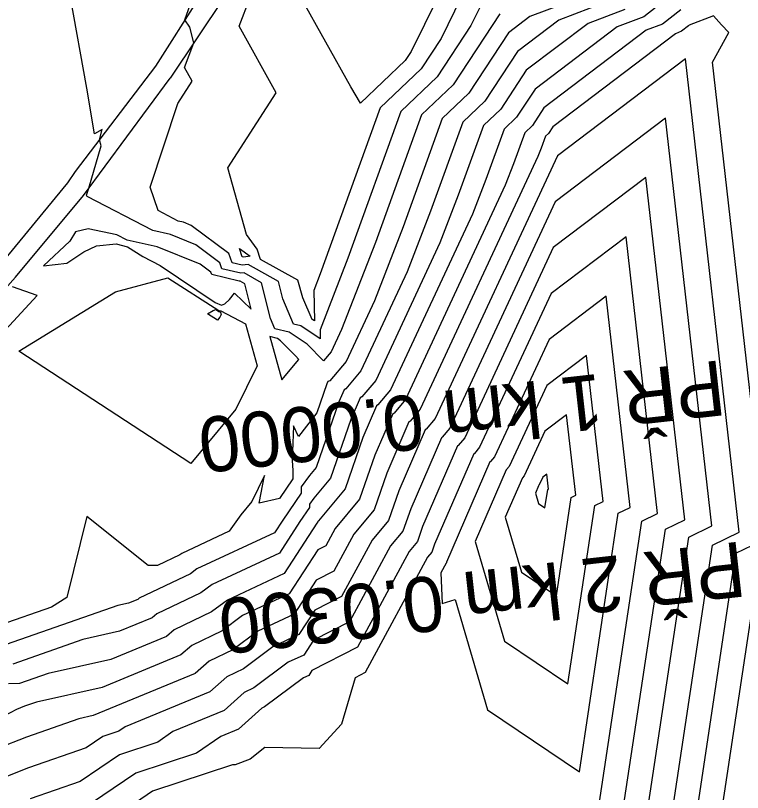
# Model space of a CAD drawing. Extents: x -549394 to -546608, y -1037055 to -1033629.
# Drawn here: x -547735.2 to -547615.7, y -1035584.9 to -1035457.1 of the extents above; entities that cross this region are included whole.
import ezdxf

# ---------------------------------------------------------------- set-up
doc = ezdxf.new("R2010")
doc.units = 0
for name, color, linetype in [('hlavni_vrst', 7, 'Continuous'), ('hrana_L', 7, 'Continuous'), ('norm_vrst', 7, 'Continuous'), ('x_popis_pricne_rezy_C111', 7, 'Continuous')]:
    doc.layers.add(name, color=color, linetype=linetype)

msp = doc.modelspace()

# ---------------------------------------------------------------- linework, layer by layer
at = {"layer": 'hlavni_vrst'}
for p, q in [((-547664.28, -1035451.11), (-547670.13, -1035463.03)), ((-547680.08, -1035468.83), (-547689.44, -1035452.02)), ((-547638.14, -1035454.93), (-547645.86, -1035457.85)), ((-547645.86, -1035457.85), (-547652.67, -1035463.03)), ((-547670.13, -1035463.03), (-547671.12, -1035464.52)), ((-547652.67, -1035463.03), (-547658.05, -1035471.18)), ((-547671.12, -1035464.52), (-547678.47, -1035471.52)), ((-547625.05, -1035464.23), (-547646.1, -1035480.2)), ((-547616.21, -1035542.07), (-547625.05, -1035464.23)), ((-547678.47, -1035471.52), (-547680.08, -1035468.83)), ((-547658.05, -1035471.18), (-547661.66, -1035474.62)), ((-547661.66, -1035474.62), (-547666.95, -1035489.27)), ((-547646.1, -1035480.2), (-547666.22, -1035523.41)), ((-547666.95, -1035489.27), (-547670.82, -1035499.26)), ((-547670.82, -1035499.26), (-547678.41, -1035515.56)), ((-547641.33, -1035513.01), (-547647.82, -1035517.94)), ((-547638.6, -1035537.02), (-547641.33, -1035513.01)), ((-547678.41, -1035515.56), (-547680.9, -1035518.5)), ((-547647.82, -1035517.94), (-547654.03, -1035531.27)), ((-547681.17, -1035518.65), (-547682.03, -1035520.64)), ((-547680.9, -1035518.5), (-547681.17, -1035518.65)), ((-547682.03, -1035520.64), (-547685.78, -1035531.46)), ((-547666.22, -1035523.41), (-547667.69, -1035525.15)), ((-547667.85, -1035525.24), (-547672.2, -1035535.3)), ((-547667.69, -1035525.15), (-547667.85, -1035525.24)), ((-547685.78, -1035531.46), (-547686.88, -1035532.78)), ((-547654.53, -1035531.83), (-547659.62, -1035543.61)), ((-547654.48, -1035531.8), (-547654.53, -1035531.83)), ((-547654.03, -1035531.27), (-547654.48, -1035531.8)), ((-547686.88, -1035532.78), (-547688.23, -1035534.65)), ((-547688.23, -1035534.65), (-547688.22, -1035535.67)), ((-547688.22, -1035535.67), (-547691.27, -1035540.11)), ((-547672.2, -1035535.3), (-547673.88, -1035540.16)), ((-547639.96, -1035537.69), (-547638.6, -1035537.02)), ((-547644.39, -1035567.05), (-547639.96, -1035537.69)), ((-547691.27, -1035540.11), (-547692.61, -1035542.19)), ((-547673.88, -1035540.16), (-547676.56, -1035543.39)), ((-547692.61, -1035542.19), (-547705.37, -1035548.14)), ((-547620.62, -1035544.22), (-547616.21, -1035542.07)), ((-547676.56, -1035543.39), (-547681.58, -1035552.67)), ((-547659.62, -1035543.61), (-547654.8, -1035560.01)), ((-547628.56, -1035596.95), (-547620.62, -1035544.22)), ((-547706.45, -1035548.95), (-547714.87, -1035552.95)), ((-547705.37, -1035548.14), (-547706.45, -1035548.95)), ((-547681.58, -1035552.67), (-547685.99, -1035554.91)), ((-547716.64, -1035553.78), (-547718.39, -1035554.17)), ((-547715.08, -1035553.14), (-547716.64, -1035553.78)), ((-547714.87, -1035552.95), (-547715.08, -1035553.14)), ((-547718.39, -1035554.17), (-547736.73, -1035560.59)), ((-547685.99, -1035554.91), (-547688.6, -1035558.94)), ((-547688.6, -1035558.94), (-547692.88, -1035560.94)), ((-547654.8, -1035560.01), (-547644.39, -1035567.05)), ((-547692.88, -1035560.94), (-547697.74, -1035564.59)), ((-547697.74, -1035564.59), (-547700.47, -1035565.89)), ((-547700.47, -1035565.89), (-547703.27, -1035568.38)), ((-547703.27, -1035568.38), (-547717.17, -1035574.12)), ((-547717.17, -1035574.12), (-547718.22, -1035574.85)), ((-547720.85, -1035575.72), (-547723.56, -1035577.55)), ((-547718.22, -1035574.85), (-547720.85, -1035575.72)), ((-547723.56, -1035577.55), (-547733.09, -1035580.87)), ((-547733.09, -1035580.87), (-547743.07, -1035584.83))]:
    msp.add_line(p, q, dxfattribs=at)
at = {"layer": 'hrana_L'}
for p, q in [((-547699.54, -1035445.41), (-547712.17, -1035465.45)), ((-547696.51, -1035447.59), (-547709.78, -1035467.43)), ((-547712.17, -1035465.45), (-547725.38, -1035482.77)), ((-547724.03, -1035486.73), (-547709.78, -1035467.43)), ((-547725.38, -1035482.77), (-547726.66, -1035484.61)), ((-547726.66, -1035484.61), (-547737.85, -1035498.19)), ((-547735.19, -1035500.12), (-547724.03, -1035486.73)), ((-547747.65, -1035514.01), (-547735.19, -1035500.12))]:
    msp.add_line(p, q, dxfattribs=at)
at = {"layer": 'norm_vrst'}
for p, q in [((-547698.44, -1035458.84), (-547694.5, -1035448.65)), ((-547723.48, -1035469.06), (-547726.4, -1035452.64)), ((-547661.36, -1035453), (-547665.23, -1035460.9)), ((-547641.26, -1035453.73), (-547650.65, -1035457.29)), ((-547627.1, -1035453.54), (-547631.91, -1035457.32)), ((-547707.37, -1035457.83), (-547706.2, -1035454.57)), ((-547658.44, -1035454.9), (-547660.33, -1035458.76)), ((-547655.57, -1035456.83), (-547663.27, -1035468.52)), ((-547635.03, -1035456.12), (-547641.07, -1035458.41)), ((-547625.83, -1035456.18), (-547628.8, -1035458.51)), ((-547706.52, -1035459.01), (-547707.37, -1035457.83)), ((-547650.65, -1035457.29), (-547654.12, -1035459.93)), ((-547631.91, -1035457.32), (-547636.28, -1035458.97)), ((-547620.46, -1035457.13), (-547624.42, -1035458.69)), ((-547619.15, -1035458.65), (-547620.46, -1035457.13)), ((-547705.86, -1035461.57), (-547706.52, -1035459.01)), ((-547692.32, -1035469.82), (-547698.44, -1035458.84)), ((-547660.33, -1035458.76), (-547665.89, -1035467.19)), ((-547641.07, -1035458.41), (-547651.22, -1035466.12)), ((-547636.28, -1035458.97), (-547649.77, -1035469.22)), ((-547628.8, -1035458.51), (-547631.49, -1035459.53)), ((-547624.56, -1035458.82), (-547625.68, -1035459.7)), ((-547624.42, -1035458.69), (-547624.56, -1035458.82)), ((-547617.94, -1035459.88), (-547619.15, -1035458.65)), ((-547654.12, -1035459.93), (-547660.66, -1035469.85)), ((-547631.49, -1035459.53), (-547648.32, -1035472.31)), ((-547626.7, -1035460.09), (-547646.87, -1035475.41)), ((-547625.68, -1035459.7), (-547626.7, -1035460.09)), ((-547620.63, -1035464.77), (-547617.94, -1035459.88)), ((-547707.44, -1035465.66), (-547705.86, -1035461.57)), ((-547665.23, -1035460.9), (-547668.5, -1035465.85)), ((-547706.18, -1035467.92), (-547707.44, -1035465.66)), ((-547668.5, -1035465.85), (-547675.25, -1035472.28)), ((-547611.73, -1035543.08), (-547620.63, -1035464.77)), ((-547665.89, -1035467.19), (-547671.85, -1035472.87)), ((-547651.22, -1035466.12), (-547655.43, -1035472.51)), ((-547708.54, -1035471.56), (-547706.18, -1035467.92)), ((-547722.23, -1035476.54), (-547723.48, -1035469.06)), ((-547663.27, -1035468.52), (-547668.45, -1035473.45)), ((-547649.77, -1035469.22), (-547652.82, -1035473.84)), ((-547700.32, -1035482.14), (-547692.32, -1035469.82)), ((-547660.66, -1035469.85), (-547665.06, -1035474.04)), ((-547713.06, -1035485.32), (-547708.54, -1035471.56)), ((-547675.25, -1035472.28), (-547685.11, -1035499.6)), ((-547671.85, -1035472.87), (-547680.57, -1035497.02)), ((-547668.45, -1035473.45), (-547676.03, -1035494.44)), ((-547655.43, -1035472.51), (-547658.27, -1035475.21)), ((-547648.32, -1035472.31), (-547650.2, -1035475.17)), ((-547665.06, -1035474.04), (-547671.49, -1035491.85)), ((-547652.82, -1035473.84), (-547654.87, -1035475.8)), ((-547628.31, -1035473.99), (-547646.45, -1035487.75)), ((-547620.69, -1035541.06), (-547628.31, -1035473.99)), ((-547720.95, -1035475.87), (-547722.23, -1035476.54)), ((-547721.4, -1035477.56), (-547720.95, -1035475.87)), ((-547658.27, -1035475.21), (-547662.41, -1035486.68)), ((-547654.87, -1035475.8), (-547657.87, -1035484.1)), ((-547650.2, -1035475.17), (-547651.47, -1035476.38)), ((-547646.87, -1035475.41), (-547647.59, -1035476.5)), ((-547651.47, -1035476.38), (-547653.33, -1035481.52)), ((-547648.08, -1035476.97), (-547648.79, -1035478.93)), ((-547647.59, -1035476.5), (-547648.08, -1035476.97)), ((-547723.13, -1035485.51), (-547721.1, -1035478.56)), ((-547721.1, -1035478.56), (-547721.4, -1035477.56)), ((-547648.79, -1035478.93), (-547649.31, -1035480.27)), ((-547649.31, -1035480.27), (-547668.66, -1035521.84)), ((-547697.25, -1035493.12), (-547700.32, -1035482.14)), ((-547653.33, -1035481.52), (-547654.68, -1035485.02)), ((-547631.56, -1035483.75), (-547646.79, -1035495.29)), ((-547625.17, -1035540.05), (-547631.56, -1035483.75)), ((-547654.68, -1035485.02), (-547671.09, -1035520.27)), ((-547657.87, -1035484.1), (-547660.06, -1035489.77)), ((-547723.51, -1035486.66), (-547723.13, -1035485.51)), ((-547711.76, -1035489.2), (-547713.06, -1035485.32)), ((-547723.45, -1035486.85), (-547723.51, -1035486.66)), ((-547712.65, -1035492.49), (-547723.45, -1035486.85)), ((-547662.41, -1035486.68), (-547665.44, -1035494.51)), ((-547646.45, -1035487.75), (-547663.78, -1035524.99)), ((-547708.46, -1035490.92), (-547711.76, -1035489.2)), ((-547660.06, -1035489.77), (-547673.53, -1035518.7)), ((-547707.57, -1035491.11), (-547708.46, -1035490.92)), ((-547706.3, -1035491.63), (-547707.57, -1035491.11)), ((-547725.36, -1035492.66), (-547726.26, -1035494.21)), ((-547723.26, -1035492.22), (-547725.36, -1035492.66)), ((-547718.53, -1035493.17), (-547723.26, -1035492.22)), ((-547709.73, -1035493.12), (-547712.65, -1035492.49)), ((-547700.13, -1035496.25), (-547706.3, -1035491.63)), ((-547671.49, -1035491.85), (-547676.2, -1035504.01)), ((-547716.84, -1035494.05), (-547718.53, -1035493.17)), ((-547705.56, -1035494.82), (-547709.73, -1035493.12)), ((-547695.49, -1035495.53), (-547697.25, -1035493.12)), ((-547634.82, -1035493.5), (-547647.13, -1035502.84)), ((-547629.65, -1035539.04), (-547634.82, -1035493.5)), ((-547726.26, -1035494.21), (-547730.58, -1035498.27)), ((-547723.99, -1035495.99), (-547721.9, -1035494.97)), ((-547721.9, -1035494.97), (-547718.66, -1035494.68)), ((-547718.66, -1035494.68), (-547716.78, -1035495.16)), ((-547711.89, -1035495.13), (-547716.84, -1035494.05)), ((-547716.78, -1035495.16), (-547714.25, -1035496.75)), ((-547704.83, -1035498), (-547711.89, -1035495.13)), ((-547701.61, -1035497.78), (-547705.56, -1035494.82)), ((-547676.03, -1035494.44), (-547681.58, -1035508.76)), ((-547665.44, -1035494.51), (-547675.97, -1035517.13)), ((-547646.79, -1035495.29), (-547661.34, -1035526.56)), ((-547726.75, -1035497.82), (-547723.99, -1035495.99)), ((-547699.59, -1035497.78), (-547700.13, -1035496.25)), ((-547697.92, -1035496.81), (-547698.4, -1035495.42)), ((-547698.4, -1035495.42), (-547696.63, -1035496.71)), ((-547694.93, -1035497.25), (-547695.49, -1035495.53)), ((-547730.58, -1035498.27), (-547726.75, -1035497.82)), ((-547714.25, -1035496.75), (-547711.43, -1035498.22)), ((-547701.27, -1035498.76), (-547701.61, -1035497.78)), ((-547697.93, -1035498.18), (-547699.59, -1035497.78)), ((-547697.67, -1035496.86), (-547697.92, -1035496.81)), ((-547696.63, -1035496.71), (-547697.67, -1035496.86)), ((-547688.8, -1035500.63), (-547694.93, -1035497.25)), ((-547680.57, -1035497.02), (-547685.13, -1035508.79)), ((-547711.43, -1035498.22), (-547702.38, -1035504.33)), ((-547703.1, -1035499.3), (-547704.83, -1035498)), ((-547698.18, -1035499.5), (-547701.27, -1035498.76)), ((-547696.97, -1035498.04), (-547697.93, -1035498.18)), ((-547691.97, -1035500.87), (-547696.97, -1035498.04)), ((-547718.76, -1035502.57), (-547710.18, -1035500.27)), ((-547710.18, -1035500.27), (-547701.8, -1035505.6)), ((-547702.95, -1035499.73), (-547703.1, -1035499.3)), ((-547698.44, -1035500.81), (-547702.95, -1035499.73)), ((-547697.63, -1035499.41), (-547698.18, -1035499.5)), ((-547694.74, -1035501.05), (-547697.63, -1035499.41)), ((-547685.11, -1035499.6), (-547686.16, -1035502.32)), ((-547698.29, -1035500.79), (-547698.44, -1035500.81)), ((-547697.51, -1035501.23), (-547698.29, -1035500.79)), ((-547696.47, -1035505.43), (-547697.51, -1035501.23)), ((-547693.28, -1035506.94), (-547694.74, -1035501.05)), ((-547691.27, -1035503.69), (-547691.97, -1035500.87)), ((-547687.96, -1035503.52), (-547688.8, -1035500.63)), ((-547731.66, -1035503.18), (-547735.69, -1035501.72)), ((-547734.65, -1035512.34), (-547718.76, -1035502.57)), ((-547700.04, -1035503.83), (-547699.22, -1035502.8)), ((-547699.22, -1035502.8), (-547696.47, -1035505.43)), ((-547686.16, -1035502.32), (-547686.05, -1035507.33)), ((-547647.13, -1035502.84), (-547658.9, -1035528.13)), ((-547738.65, -1035510.72), (-547731.66, -1035503.18)), ((-547700.81, -1035504.52), (-547700.04, -1035503.83)), ((-547689.51, -1035507.87), (-547691.27, -1035503.69)), ((-547686.45, -1035507.12), (-547687.96, -1035503.52)), ((-547676.2, -1035504.01), (-547680.85, -1035513.99)), ((-547638.07, -1035503.26), (-547647.48, -1035510.39)), ((-547634.12, -1035538.03), (-547638.07, -1035503.26)), ((-547702.72, -1035505.62), (-547702.24, -1035505.49)), ((-547702.38, -1035504.33), (-547701.34, -1035504.75)), ((-547702.24, -1035505.49), (-547701.76, -1035505.79)), ((-547701.34, -1035504.75), (-547700.81, -1035504.52)), ((-547703.62, -1035506.17), (-547702.72, -1035505.62)), ((-547702.02, -1035507.22), (-547703.62, -1035506.17)), ((-547701.6, -1035506.71), (-547702.02, -1035507.22)), ((-547701.8, -1035505.6), (-547701.44, -1035505.67)), ((-547701.76, -1035505.79), (-547701.74, -1035505.79)), ((-547701.74, -1035505.79), (-547701.51, -1035505.92)), ((-547701.41, -1035506.31), (-547701.6, -1035506.71)), ((-547701.51, -1035505.92), (-547701.41, -1035506.31)), ((-547701.44, -1035505.67), (-547697.39, -1035507.83)), ((-547697.39, -1035507.83), (-547695.49, -1035514.75)), ((-547692.58, -1035508.62), (-547693.28, -1035506.94)), ((-547688.27, -1035508.17), (-547689.51, -1035507.87)), ((-547686.33, -1035507.14), (-547686.45, -1035507.12)), ((-547686.05, -1035507.33), (-547686.33, -1035507.14)), ((-547690.21, -1035509.2), (-547692.58, -1035508.62)), ((-547687.24, -1035511.17), (-547690.21, -1035509.2)), ((-547685.1, -1035510.27), (-547688.27, -1035508.17)), ((-547685.13, -1035508.79), (-547685.1, -1035510.27)), ((-547681.58, -1035508.76), (-547683.29, -1035512.42)), ((-547692.15, -1035510.23), (-547693.4, -1035509.92)), ((-547693.4, -1035509.92), (-547691.39, -1035517.05)), ((-547691.62, -1035510.59), (-547692.15, -1035510.23)), ((-547689.17, -1035513.08), (-547691.62, -1035510.59)), ((-547647.48, -1035510.39), (-547656.47, -1035529.7)), ((-547684.54, -1035513.91), (-547687.24, -1035511.17)), ((-547706.39, -1035530.82), (-547734.65, -1035512.34)), ((-547688.61, -1035513.67), (-547689.17, -1035513.08)), ((-547683.29, -1035512.42), (-547684.54, -1035513.91)), ((-547691.39, -1035517.05), (-547688.61, -1035513.67)), ((-547680.85, -1035513.99), (-547683.54, -1035517.17)), ((-547695.49, -1035514.75), (-547698.97, -1035521.88)), ((-547684, -1035517.7), (-547685.65, -1035522.48)), ((-547683.84, -1035517.33), (-547684, -1035517.7)), ((-547683.54, -1035517.17), (-547683.84, -1035517.33)), ((-547675.97, -1035517.13), (-547678.26, -1035519.83)), ((-547673.53, -1035518.7), (-547675.62, -1035521.16)), ((-547678.51, -1035519.97), (-547680.06, -1035523.57)), ((-547678.26, -1035519.83), (-547678.51, -1035519.97)), ((-547671.09, -1035520.27), (-547672.97, -1035522.49)), ((-547698.97, -1035521.88), (-547706.39, -1035530.82)), ((-547675.84, -1035521.29), (-547678.1, -1035526.5)), ((-547675.62, -1035521.16), (-547675.84, -1035521.29)), ((-547668.66, -1035521.84), (-547670.33, -1035523.82)), ((-547685.65, -1035522.48), (-547688.65, -1035526.38)), ((-547673.18, -1035522.61), (-547676.13, -1035529.43)), ((-547672.97, -1035522.49), (-547673.18, -1035522.61)), ((-547644.59, -1035522.77), (-547648.17, -1035525.49)), ((-547643.08, -1035536.01), (-547644.59, -1035522.77)), ((-547689.49, -1035524.61), (-547689.71, -1035530.31)), ((-547688.65, -1035526.38), (-547689.49, -1035524.61)), ((-547680.06, -1035523.57), (-547683.4, -1035533.2)), ((-547670.52, -1035523.92), (-547674.16, -1035532.36)), ((-547670.33, -1035523.82), (-547670.52, -1035523.92)), ((-547663.78, -1035524.99), (-547665.05, -1035526.48)), ((-547648.17, -1035525.49), (-547651.59, -1035532.84)), ((-547678.1, -1035526.5), (-547681.02, -1035534.94)), ((-547665.19, -1035526.56), (-547670.23, -1035538.23)), ((-547665.05, -1035526.48), (-547665.19, -1035526.56)), ((-547661.34, -1035526.56), (-547662.41, -1035527.81)), ((-547662.52, -1035527.88), (-547668.26, -1035541.16)), ((-547662.41, -1035527.81), (-547662.52, -1035527.88)), ((-547658.9, -1035528.13), (-547659.76, -1035529.14)), ((-547676.13, -1035529.43), (-547678.64, -1035536.68)), ((-547659.86, -1035529.19), (-547666.29, -1035544.09)), ((-547659.76, -1035529.14), (-547659.86, -1035529.19)), ((-547656.47, -1035529.7), (-547657.12, -1035530.47)), ((-547689.71, -1035530.31), (-547689.6, -1035531.93)), ((-547657.2, -1035530.51), (-547664.33, -1035547.03)), ((-547657.12, -1035530.47), (-547657.2, -1035530.51)), ((-547689.6, -1035531.93), (-547689.6, -1035533.31)), ((-547674.16, -1035532.36), (-547676.26, -1035538.42)), ((-547694.26, -1035532.79), (-547696.34, -1035537.05)), ((-547695.16, -1035537.3), (-547694.26, -1035532.79)), ((-547689.6, -1035533.31), (-547691.82, -1035536.56)), ((-547683.4, -1035533.2), (-547686.14, -1035536.49)), ((-547651.87, -1035533.15), (-547654.67, -1035539.65)), ((-547651.84, -1035533.13), (-547651.87, -1035533.15)), ((-547651.59, -1035532.84), (-547651.84, -1035533.13)), ((-547648.51, -1035533.03), (-547649.15, -1035534.41)), ((-547647.84, -1035532.53), (-547648.51, -1035533.03)), ((-547647.56, -1035535), (-547647.84, -1035532.53)), ((-547649.2, -1035534.47), (-547649.73, -1035535.68)), ((-547649.15, -1035534.41), (-547649.2, -1035534.46)), ((-547649.2, -1035534.46), (-547649.2, -1035534.47)), ((-547681.02, -1035534.94), (-547685.4, -1035540.2)), ((-547649.73, -1035535.68), (-547649.23, -1035537.37)), ((-547648.16, -1035538.1), (-547647.7, -1035535.07)), ((-547647.7, -1035535.07), (-547647.56, -1035535)), ((-547643.83, -1035536.38), (-547643.08, -1035536.01)), ((-547696.34, -1035537.05), (-547698.18, -1035539.26)), ((-547691.82, -1035536.56), (-547695.16, -1035537.3)), ((-547686.14, -1035536.49), (-547686.85, -1035537.48)), ((-547678.64, -1035536.68), (-547682.64, -1035541.49)), ((-547649.23, -1035537.37), (-547648.16, -1035538.1)), ((-547646.27, -1035552.57), (-547643.83, -1035536.38)), ((-547686.85, -1035538.02), (-547688.46, -1035540.36)), ((-547686.85, -1035537.48), (-547686.85, -1035538.02)), ((-547676.26, -1035538.42), (-547679.6, -1035542.44)), ((-547670.23, -1035538.23), (-547671.5, -1035541.9)), ((-547636.09, -1035538.99), (-547634.12, -1035538.03)), ((-547723.49, -1035539.49), (-547726.74, -1035552.86)), ((-547713.37, -1035547.59), (-547723.49, -1035539.49)), ((-547698.18, -1035539.26), (-547700.09, -1035541.95)), ((-547654.67, -1035539.65), (-547652.02, -1035548.69)), ((-547642.5, -1035581.52), (-547636.09, -1035538.99)), ((-547632.22, -1035540.3), (-547629.65, -1035539.04)), ((-547688.46, -1035540.36), (-547691.81, -1035545.54)), ((-547685.65, -1035540.62), (-547691.01, -1035548.89)), ((-547685.47, -1035540.37), (-547685.65, -1035540.62)), ((-547685.4, -1035540.2), (-547685.48, -1035540.31)), ((-547685.48, -1035540.31), (-547685.47, -1035540.37)), ((-547668.26, -1035541.16), (-547669.12, -1035543.64)), ((-547640.62, -1035596), (-547632.22, -1035540.3)), ((-547628.35, -1035541.61), (-547625.17, -1035540.05)), ((-547624.49, -1035542.91), (-547620.69, -1035541.06)), ((-547700.09, -1035541.95), (-547707.87, -1035545.58)), ((-547682.64, -1035541.49), (-547684.17, -1035544.32)), ((-547679.6, -1035542.44), (-547682.88, -1035548.5)), ((-547671.5, -1035541.9), (-547673.53, -1035544.33)), ((-547637.23, -1035600.54), (-547628.35, -1035541.61)), ((-547669.12, -1035543.64), (-547670.49, -1035545.28)), ((-547632.9, -1035598.75), (-547624.49, -1035542.91)), ((-547616.75, -1035545.53), (-547611.73, -1035543.08)), ((-547685.52, -1035545.01), (-547690.21, -1035552.24)), ((-547684.17, -1035544.32), (-547685.52, -1035545.01)), ((-547673.53, -1035544.33), (-547680.29, -1035556.85)), ((-547666.29, -1035544.09), (-547666.74, -1035545.38)), ((-547708.19, -1035545.82), (-547711.88, -1035547.58)), ((-547707.87, -1035545.58), (-547708.19, -1035545.82)), ((-547691.81, -1035545.54), (-547702.87, -1035550.7)), ((-547670.49, -1035545.28), (-547678.99, -1035561.02)), ((-547667.45, -1035546.23), (-547677.7, -1035565.2)), ((-547666.74, -1035545.38), (-547667.45, -1035546.23)), ((-547624.22, -1035595.15), (-547616.75, -1035545.53)), ((-547711.88, -1035547.58), (-547713.37, -1035547.59)), ((-547664.41, -1035547.18), (-547665.28, -1035548.8)), ((-547664.36, -1035547.12), (-547664.41, -1035547.18)), ((-547664.33, -1035547.03), (-547664.36, -1035547.12)), ((-547619.89, -1035593.35), (-547612.88, -1035546.84)), ((-547691.01, -1035548.89), (-547700.37, -1035553.26)), ((-547682.88, -1035548.5), (-547685.75, -1035549.96)), ((-547665.28, -1035548.8), (-547665.06, -1035553.81)), ((-547652.02, -1035548.69), (-547646.27, -1035552.57)), ((-547685.75, -1035549.96), (-547689.4, -1035555.59)), ((-547702.87, -1035550.7), (-547704.71, -1035552.08)), ((-547704.71, -1035552.08), (-547711.99, -1035555.54)), ((-547690.21, -1035552.24), (-547697.87, -1035555.82)), ((-547726.74, -1035552.86), (-547729.27, -1035554.41)), ((-547700.37, -1035553.26), (-547702.96, -1035555.21)), ((-547665.06, -1035553.81), (-547662.92, -1035553.17)), ((-547662.92, -1035553.17), (-547657.59, -1035571.33)), ((-547729.27, -1035554.41), (-547737.81, -1035557.4)), ((-547702.96, -1035555.21), (-547709.11, -1035558.13)), ((-547712.72, -1035556.19), (-547718.09, -1035558.4)), ((-547711.99, -1035555.54), (-547712.72, -1035556.19)), ((-547697.87, -1035555.82), (-547701.22, -1035558.34)), ((-547689.4, -1035555.59), (-547695.38, -1035558.38)), ((-547680.29, -1035556.85), (-547686.22, -1035559.86)), ((-547718.09, -1035558.4), (-547724.11, -1035559.75)), ((-547709.11, -1035558.13), (-547710.36, -1035559.24)), ((-547701.22, -1035558.34), (-547706.23, -1035560.71)), ((-547695.38, -1035558.38), (-547699.48, -1035561.46)), ((-547724.11, -1035559.75), (-547735.65, -1035563.79)), ((-547710.36, -1035559.24), (-547719.53, -1035563.03)), ((-547686.22, -1035559.86), (-547687.8, -1035562.3)), ((-547706.23, -1035560.71), (-547708, -1035562.28)), ((-547699.48, -1035561.46), (-547703.35, -1035563.3)), ((-547678.99, -1035561.02), (-547686.46, -1035564.82)), ((-547719.53, -1035563.03), (-547729.82, -1035565.32)), ((-547708, -1035562.28), (-547720.97, -1035567.65)), ((-547687.8, -1035562.3), (-547690.38, -1035563.5)), ((-547703.35, -1035563.3), (-547705.64, -1035565.33)), ((-547690.38, -1035563.5), (-547696, -1035567.72)), ((-547729.82, -1035565.32), (-547734.57, -1035566.98)), ((-547705.64, -1035565.33), (-547722.42, -1035572.27)), ((-547686.46, -1035564.82), (-547687, -1035565.65)), ((-547677.7, -1035565.2), (-547679.35, -1035566.04)), ((-547687.88, -1035566.06), (-547694.26, -1035570.85)), ((-547687, -1035565.65), (-547687.88, -1035566.06)), ((-547679.35, -1035566.04), (-547681.63, -1035573.7)), ((-547734.57, -1035566.98), (-547736.34, -1035567.03)), ((-547720.97, -1035567.65), (-547731.73, -1035570.04)), ((-547696, -1035567.72), (-547697.59, -1035568.48)), ((-547697.59, -1035568.48), (-547700.91, -1035571.43)), ((-547731.73, -1035570.04), (-547733.72, -1035570.74)), ((-547735.03, -1035571.26), (-547750.35, -1035579.21)), ((-547733.72, -1035570.74), (-547735.03, -1035571.26)), ((-547700.91, -1035571.43), (-547709.31, -1035574.9)), ((-547694.71, -1035571.06), (-547698.55, -1035574.47)), ((-547694.26, -1035570.85), (-547694.71, -1035571.06)), ((-547657.59, -1035571.33), (-547642.5, -1035581.52)), ((-547724.77, -1035572.79), (-547733.41, -1035575.81)), ((-547722.42, -1035572.27), (-547724.77, -1035572.79)), ((-547698.55, -1035574.47), (-547701.46, -1035575.68)), ((-547681.63, -1035573.7), (-547685.25, -1035577.66)), ((-547733.41, -1035575.81), (-547739.05, -1035578.04)), ((-547709.31, -1035574.9), (-547711.82, -1035576.65)), ((-547701.46, -1035575.68), (-547705.43, -1035578.44)), ((-547711.82, -1035576.65), (-547718.13, -1035578.72)), ((-547694.19, -1035577.51), (-547696.64, -1035579.43)), ((-547685.25, -1035577.66), (-547694.19, -1035577.51)), ((-547718.13, -1035578.72), (-547724.58, -1035583.08)), ((-547705.43, -1035578.44), (-547715.4, -1035581.71)), ((-547696.64, -1035579.43), (-547699.11, -1035580.36)), ((-547699.52, -1035580.39), (-547712.67, -1035584.71)), ((-547699.11, -1035580.36), (-547699.52, -1035580.39)), ((-547715.4, -1035581.71), (-547725.61, -1035588.62)), ((-547724.58, -1035583.08), (-547732.77, -1035585.94)), ((-547712.67, -1035584.71), (-547726.64, -1035594.15))]:
    msp.add_line(p, q, dxfattribs=at)

# ---------------------------------------------------------------- texts
at = {"layer": 'x_popis_pricne_rezy_C111'}
for s, p in [('PŘ 1 km 0.0000', (-547619.14, -1035513.78)), ('PŘ 2 km 0.0300', (-547615.83, -1035543.6))]:
    msp.add_text(s, height=9.0627, rotation=186.3516, dxfattribs=at).set_placement(p)

doc.saveas('drawing.dxf')
